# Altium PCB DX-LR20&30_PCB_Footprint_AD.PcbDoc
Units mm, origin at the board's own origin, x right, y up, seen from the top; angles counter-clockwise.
Board outline 152.4 x 101.6 mm, 2 copper layers (Top Layer, Bottom Layer); 1 components, 0 nets, 22 pads, 0 vias.
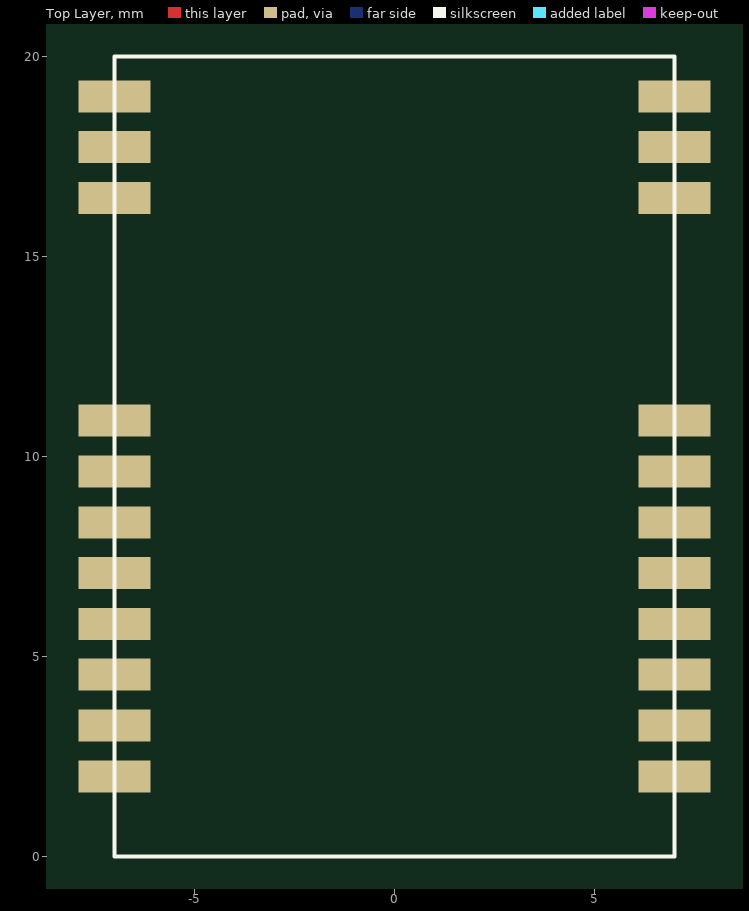
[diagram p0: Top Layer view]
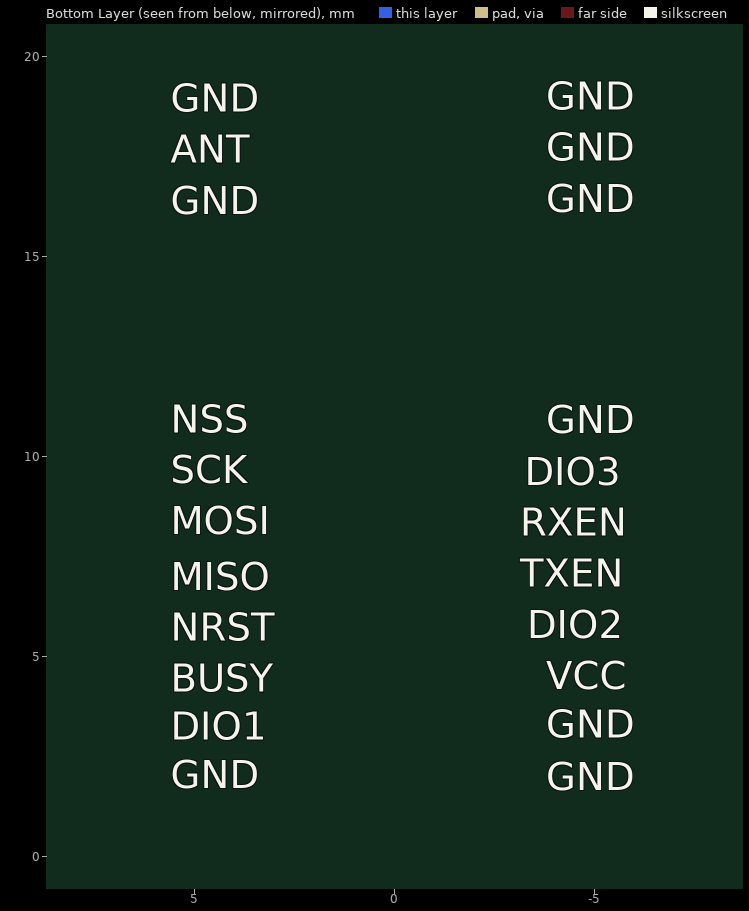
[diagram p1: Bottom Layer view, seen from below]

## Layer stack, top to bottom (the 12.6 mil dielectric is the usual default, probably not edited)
Top Solder: solder mask 0.0102, Solder Resist, Dk 3.5
Top Layer: signal copper 0.0356
Dielectric 1: dielectric 0.32, FR-4, Dk 4.8
Bottom Layer: signal copper 0.0356
Bottom Solder: solder mask 0.0102, Solder Resist, Dk 3.5

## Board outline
-61.102,-42.672 91.298,-42.672 91.298,58.928 -61.102,58.928

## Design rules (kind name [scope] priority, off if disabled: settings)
Clearance [All] p1: gap=0.254 ignorepadtopadclearanceinfootprint=FALSE except(0: Arc-Hole Track-Hole SMDPad-Hole THPad-Hole Via-Hole Fill-Hole Poly-Hole Region-Hole Text-Hole)
PolygonConnect [All] p1: connectstyle=Relief reliefconductorwidth=0.254 reliefentries=4 polygonreliefangle="90 Angle" airgapwidth=0.254
RoutingVias [All] p1: holewidth=0.711 width=1.27 viastyle="Through Hole" minholewidth=0.711 minwidth=1.27 maxholewidth=0.711 maxwidth=1.27
SolderMaskExpansion [All] p1: expansion=0.102 istentingtop=FALSE
Width [All] p1: maxlimit=0.254 minlimit=0.254 preferedwidth=0.254
30 further rules are at their usual default settings.

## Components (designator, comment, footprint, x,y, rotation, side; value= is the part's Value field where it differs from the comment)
U? "" PE220-400M22S -7,19 r90 top

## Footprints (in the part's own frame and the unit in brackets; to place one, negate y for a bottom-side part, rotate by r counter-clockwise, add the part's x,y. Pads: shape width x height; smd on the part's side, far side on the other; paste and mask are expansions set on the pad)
PE220-400M22S [mm] "20mm*14mm*2.8mm-S"
  rect 0.8x1.8 smd: 1(0,0) 2(-1.27,0) 3(-2.54,0) 4(-8.11,0) 5(-9.38,0) 6(-10.65,0) 7(-11.92,0) 8(-13.19,0) 9(-14.46,0) 10(-15.73,0) 11(-17,0) 12(-17,-14) 13(-15.73,-14) 14(-14.46,-14) 15(-13.19,-14) 16(-11.92,-14) 17(-10.65,-14) 18(-9.38,-14) 19(-8.11,-14) 20(-2.54,-14) 21(-1.27,-14) 22(0,-14)
  silkscreen extent -19,-14 1,0

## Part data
U?: library part LLCC68

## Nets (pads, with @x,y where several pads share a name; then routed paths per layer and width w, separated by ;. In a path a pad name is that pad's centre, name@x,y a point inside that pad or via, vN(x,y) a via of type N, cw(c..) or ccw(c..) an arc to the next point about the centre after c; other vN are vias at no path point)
pads on no net: U?.1 U?.2 U?.3 U?.4 U?.5 U?.6 U?.7 U?.8 U?.9 U?.10 U?.11 U?.12 U?.13 U?.14 U?.15 U?.16 U?.17 U?.18 U?.19 U?.20 U?.21 U?.22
